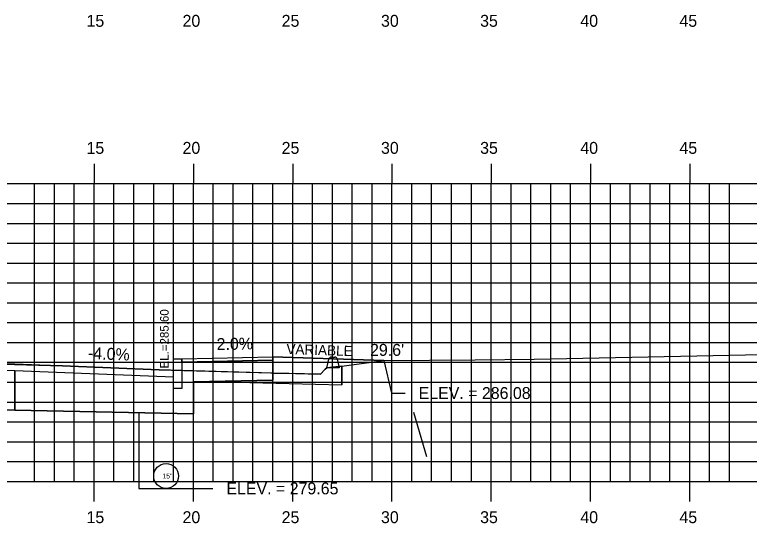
# Model space of a CAD drawing. Extents: x 852672 to 852842, y 366268 to 366378.
# Drawn here: x 852766.1 to 852803.09, y 366325.22 to 366350.84 of the extents above; entities that cross this region are included whole.
import ezdxf

# ---------------------------------------------------------------- set-up
doc = ezdxf.new("R2010")
doc.units = 0
for name, color, linetype in [('ANNOTATION', 7, 'Continuous'), ('D_Curb_Type1_Rt', 7, 'Continuous'), ('D_Roadway_Edge_Shoulder', 7, 'Continuous'), ('D_Roadway_FinishedGrade', 7, 'Continuous'), ('D_Roadway_Sidewalks_Paved', 7, 'Continuous'), ('D_Roadway_SubGrade', 7, 'Continuous'), ('D_Text_Standard', 7, 'Continuous'), ('H_V ANNOTATION', 7, 'Continuous'), ('JUNK COM EXC', 7, 'Continuous'), ('JUNK FILL', 7, 'Continuous'), ('junk grubnfill', 7, 'Continuous'), ('junk strct exc', 7, 'Continuous'), ('MAJOR', 7, 'Continuous'), ('MINOR', 7, 'Continuous'), ('PDRAIN', 7, 'Continuous'), ('S_Curb_Type_3', 7, 'Continuous'), ('S_Roadway_Centerline', 7, 'Continuous')]:
    doc.layers.add(name, color=color, linetype=linetype)

msp = doc.modelspace()

# ---------------------------------------------------------------- linework, layer by layer
at = {"layer": 'ANNOTATION'}
msp.add_line((852786.854, 366328.559), (852786.205, 366330.803), dxfattribs=at)
at = {"layer": 'D_Curb_Type1_Rt'}
msp.add_lwpolyline([(852774.513, 366333.508), (852774.513, 366332.008), (852774.096, 366332.008), (852774.096, 366333.508)], close=True, dxfattribs=at)
at = {"layer": 'D_Roadway_Edge_Shoulder'}
msp.add_lwpolyline([(852736.096, 366332.925), (852744.096, 366333.245), (852755.096, 366333.464), (852766.096, 366333.245), (852774.096, 366332.924)], dxfattribs=at)
at = {"layer": 'D_Roadway_FinishedGrade'}
msp.add_line((852779.101, 366333.599), (852784.69, 366333.411), dxfattribs=at)
at = {"layer": 'D_Roadway_Sidewalks_Paved'}
msp.add_lwpolyline([(852774.513, 366333.507), (852779.101, 366333.599), (852779.101, 366333.433), (852774.513, 366333.341)], close=True, dxfattribs=at)
at = {"layer": 'D_Roadway_SubGrade'}
msp.add_line((852782.579, 366333.14), (852782.579, 366332.196), dxfattribs=at)
for points in [[(852774.513, 366333.341), (852779.101, 366333.433), (852779.101, 366332.433), (852775.096, 366332.352), (852775.096, 366330.732)], [(852775.096, 366330.732), (852766.106, 366330.912), (852766.106, 366332.912), (852774.096, 366332.592)], [(852775.94, 366332.369), (852782.579, 366332.196)]]:
    msp.add_lwpolyline(points, dxfattribs=at)
msp.add_lwpolyline([(852744.106, 366330.912), (852744.106, 366332.912), (852755.106, 366333.132), (852766.106, 366332.912), (852766.106, 366330.912), (852755.106, 366331.132)], close=True, dxfattribs=at)
at = {"layer": 'D_Text_Standard'}
for points in [[(852784.69, 366333.411), (852785.078, 366331.779), (852785.758, 366331.779)], [(852775.096, 366326.977), (852775.398, 366326.977), (852776.078, 366326.977)]]:
    msp.add_lwpolyline(points, dxfattribs=at)
at = {"layer": 'JUNK COM EXC'}
msp.add_lwpolyline([(852735.096, 366332.469), (852735.096, 366330.732), (852744.106, 366330.912), (852755.106, 366331.132), (852766.106, 366330.912), (852775.096, 366330.732), (852775.096, 366332.352), (852779.101, 366332.433), (852779.101, 366332.787), (852775.096, 366332.902), (852773.379, 366332.951), (852768.512, 366333.143), (852758.198, 366333.438), (852755.238, 366333.514), (852745.742, 366333.256), (852743.139, 366333.207), (852741.706, 366333.107), (852736.999, 366332.744)], close=True, dxfattribs=at)
at = {"layer": 'JUNK FILL'}
msp.add_lwpolyline([(852779.101, 366332.787), (852780.241, 366332.757), (852781.492, 366332.725), (852781.726, 366332.983), (852781.821, 366333.046), (852782.579, 366333.14), (852784.69, 366333.411), (852779.101, 366333.599)], close=True, dxfattribs=at)
at = {"layer": 'junk grubnfill'}
msp.add_lwpolyline([(852779.101, 366332.787), (852779.101, 366332.433), (852775.94, 366332.369), (852782.579, 366332.196), (852782.579, 366333.14), (852781.821, 366333.046), (852781.726, 366332.983), (852781.492, 366332.725), (852779.101, 366332.787)], dxfattribs=at)
at = {"layer": 'junk strct exc'}
msp.add_lwpolyline([(852772.346, 366330.787), (852772.346, 366326.977), (852775.096, 366326.977), (852775.096, 366330.732)], close=True, dxfattribs=at)
at = {"layer": 'MAJOR'}
for p, q in [((852770.096, 366343.329), (852770.096, 366342.327)), ((852775.096, 366343.329), (852775.096, 366342.327)), ((852780.096, 366343.329), (852780.096, 366342.327)), ((852785.096, 366343.329), (852785.096, 366342.327)), ((852790.096, 366343.329), (852790.096, 366342.327)), ((852795.096, 366343.329), (852795.096, 366342.327)), ((852800.096, 366343.329), (852800.096, 366342.327)), ((852685.096, 366342.327), (852825.096, 366342.327)), ((852685.096, 366342.327), (852825.096, 366342.327)), ((852770.096, 366327.327), (852770.096, 366342.327)), ((852775.096, 366327.327), (852775.096, 366342.327)), ((852780.096, 366327.327), (852780.096, 366342.327)), ((852785.096, 366327.327), (852785.096, 366342.327)), ((852790.096, 366327.327), (852790.096, 366342.327)), ((852795.096, 366327.327), (852795.096, 366342.327)), ((852800.096, 366327.327), (852800.096, 366342.327)), ((852685.096, 366337.327), (852825.096, 366337.327)), ((852685.096, 366332.327), (852825.096, 366332.327)), ((852685.096, 366327.327), (852825.096, 366327.327)), ((852685.096, 366327.327), (852825.096, 366327.327)), ((852770.096, 366326.325), (852770.096, 366327.327)), ((852775.096, 366326.325), (852775.096, 366327.327)), ((852780.096, 366326.325), (852780.096, 366327.327)), ((852785.096, 366326.325), (852785.096, 366327.327)), ((852790.096, 366326.325), (852790.096, 366327.327)), ((852795.096, 366326.325), (852795.096, 366327.327)), ((852800.096, 366326.325), (852800.096, 366327.327))]:
    msp.add_line(p, q, dxfattribs=at)
at = {"layer": 'MINOR'}
for p, q in [((852767.096, 366327.327), (852767.096, 366342.327)), ((852768.096, 366327.327), (852768.096, 366342.327)), ((852769.096, 366327.327), (852769.096, 366342.327)), ((852771.096, 366327.327), (852771.096, 366342.327)), ((852772.096, 366327.327), (852772.096, 366342.327)), ((852773.096, 366327.327), (852773.096, 366342.327)), ((852774.096, 366327.327), (852774.096, 366342.327)), ((852776.096, 366327.327), (852776.096, 366342.327)), ((852777.096, 366327.327), (852777.096, 366342.327)), ((852778.096, 366327.327), (852778.096, 366342.327)), ((852779.096, 366327.327), (852779.096, 366342.327)), ((852781.096, 366327.327), (852781.096, 366342.327)), ((852782.096, 366327.327), (852782.096, 366342.327)), ((852783.096, 366327.327), (852783.096, 366342.327)), ((852784.096, 366327.327), (852784.096, 366342.327)), ((852786.096, 366327.327), (852786.096, 366342.327)), ((852787.096, 366327.327), (852787.096, 366342.327)), ((852788.096, 366327.327), (852788.096, 366342.327)), ((852789.096, 366327.327), (852789.096, 366342.327)), ((852791.096, 366327.327), (852791.096, 366342.327)), ((852792.096, 366327.327), (852792.096, 366342.327)), ((852793.096, 366327.327), (852793.096, 366342.327)), ((852794.096, 366327.327), (852794.096, 366342.327)), ((852796.096, 366327.327), (852796.096, 366342.327)), ((852797.096, 366327.327), (852797.096, 366342.327)), ((852798.096, 366327.327), (852798.096, 366342.327)), ((852799.096, 366327.327), (852799.096, 366342.327)), ((852801.096, 366327.327), (852801.096, 366342.327)), ((852802.096, 366327.327), (852802.096, 366342.327)), ((852685.096, 366341.327), (852825.096, 366341.327)), ((852685.096, 366340.327), (852825.096, 366340.327)), ((852685.096, 366339.327), (852825.096, 366339.327)), ((852685.096, 366338.327), (852825.096, 366338.327)), ((852685.096, 366336.327), (852825.096, 366336.327)), ((852685.096, 366335.327), (852825.096, 366335.327)), ((852685.096, 366334.327), (852825.096, 366334.327)), ((852685.096, 366333.327), (852825.096, 366333.327)), ((852685.096, 366331.327), (852825.096, 366331.327)), ((852685.096, 366330.327), (852825.096, 366330.327)), ((852685.096, 366329.327), (852825.096, 366329.327)), ((852685.096, 366328.327), (852825.096, 366328.327))]:
    msp.add_line(p, q, dxfattribs=at)
at = {"layer": 'PDRAIN'}
msp.add_lwpolyline([(852772.346, 366330.787), (852772.346, 366326.977), (852775.096, 366326.977), (852775.096, 366330.732)], dxfattribs=at)
msp.add_circle((852773.721, 366327.602), 0.625, dxfattribs=at)
at = {"layer": 'S_Curb_Type_3'}
for points in [[(852782.046, 366333.588), (852782.222, 366333.588)], [(852782.344, 366333.491), (852782.446, 366333.046), (852781.821, 366333.046), (852781.924, 366333.491)]]:
    msp.add_lwpolyline(points, dxfattribs=at)
for centre, start, end in [((852782.046, 366333.463), 90, 167.0054), ((852782.222, 366333.463), 12.9946, 90)]:
    msp.add_arc(centre, 0.125, start, end, dxfattribs=at)
at = {"layer": 'S_Roadway_Centerline'}
msp.add_lwpolyline([(852726.107, 366332.417), (852731.078, 366332.617), (852731.506, 366332.605), (852734.129, 366332.331), (852734.667, 366332.407), (852736.999, 366332.744), (852741.706, 366333.107), (852743.139, 366333.207), (852745.742, 366333.256), (852755.238, 366333.514), (852758.198, 366333.438), (852768.512, 366333.143), (852773.379, 366332.951), (852778.991, 366332.79), (852781.492, 366332.725), (852781.726, 366332.983), (852781.821, 366333.046), (852782.579, 366333.14), (852784.69, 366333.411), (852789.288, 366333.459), (852792.255, 366333.487), (852804.55, 366333.744)], dxfattribs=at)

# ---------------------------------------------------------------- texts
at = {"layer": 'ANNOTATION'}
for s, rotation, p in [('2.0%', 1.1481, (852776.271, 366333.943)), ('-4.0%', 357.7083, (852769.782, 366333.498))]:
    msp.add_text(s, height=0.6, rotation=rotation, dxfattribs=at).set_placement(p)
at = {"layer": 'D_Text_Standard'}
for s, height, rotation, p in [(' EL.=285.60', 0.4335, 90, (852773.851, 366332.856)), ('VARIABLE', 0.51, 358.1397, (852779.774, 366333.747))]:
    msp.add_text(s, height=height, rotation=rotation, dxfattribs=at).set_placement(p)
for s, p in [("29.6'", (852783.993, 366333.653)), ('ELEV. = 286.08', (852786.438, 366331.479)), ('ELEV. = 279.65', (852776.758, 366326.677))]:
    msp.add_text(s, height=0.6, dxfattribs=at).set_placement(p)
at = {"layer": 'H_V ANNOTATION'}
for s, p in [('15', (852769.714, 366350.227)), ('20', (852774.55, 366350.227)), ('25', (852779.542, 366350.227)), ('30', (852784.545, 366350.227)), ('35', (852789.537, 366350.227)), ('40', (852794.583, 366350.227)), ('45', (852799.575, 366350.227)), ('15', (852769.714, 366343.827)), ('20', (852774.55, 366343.827)), ('25', (852779.542, 366343.827)), ('30', (852784.545, 366343.827)), ('35', (852789.537, 366343.827)), ('40', (852794.583, 366343.827)), ('45', (852799.575, 366343.827)), ('15', (852769.714, 366325.227)), ('20', (852774.55, 366325.227)), ('25', (852779.542, 366325.227)), ('30', (852784.545, 366325.227)), ('35', (852789.537, 366325.227)), ('40', (852794.583, 366325.227)), ('45', (852799.575, 366325.227))]:
    msp.add_text(s, height=0.6, dxfattribs=at).set_placement(p)
at = {"layer": 'PDRAIN'}
msp.add_text('15"', height=0.25, dxfattribs=at).set_placement((852773.534, 366327.477))

doc.saveas('drawing.dxf')
